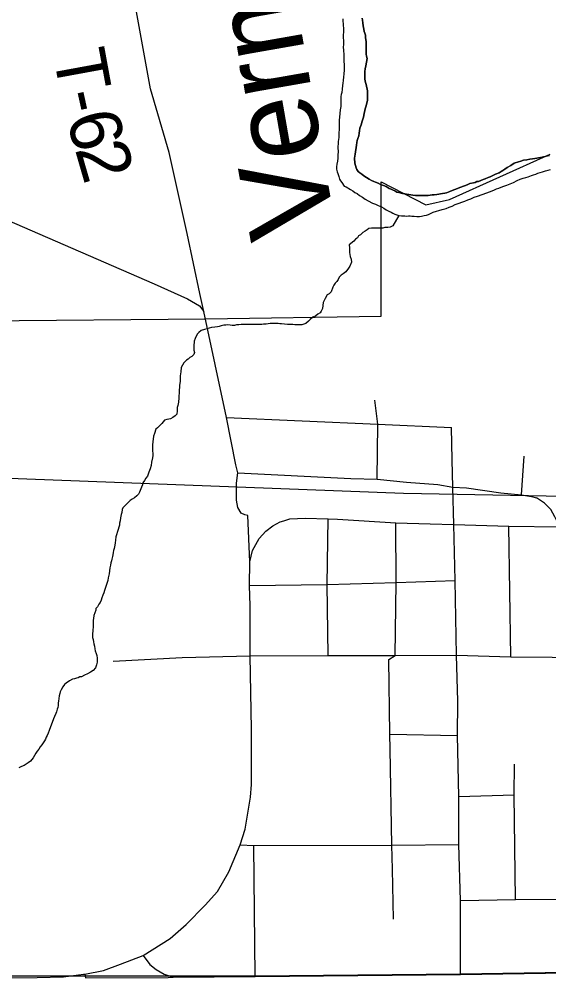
# Model space of a CAD drawing. Extents: x 0 to 34, y 0 to 22.
# Drawn here: x 4.314 to 4.895, y 17.722 to 18.774 of the extents above; entities that cross this region are included whole.
import ezdxf

# ---------------------------------------------------------------- set-up
doc = ezdxf.new("R2010")
doc.units = 0
for name, color, linetype in [('GM_X_City_Street', 7, 'Continuous'), ('GM_X_Corporation', 7, 'Continuous'), ('GM_X_Interchange_Ramps', 7, 'Continuous'), ('GM_X_Major_River', 7, 'Continuous'), ('GM_X_Major_River_Text', 7, 'Continuous'), ('GM_X_Minor_River', 7, 'Continuous'), ('GM_X_Rail_Line', 7, 'Continuous'), ('GM_X_State_Route', 7, 'Continuous'), ('GM_X_Township_Road', 7, 'Continuous'), ('GM_X_Township_Road_Text', 7, 'Continuous'), ('GM_X_US_Route', 7, 'Continuous')]:
    doc.layers.add(name, color=color, linetype=linetype)

msp = doc.modelspace()

# ---------------------------------------------------------------- linework, layer by layer
at = {"layer": 'GM_X_City_Street'}
for p, q in [((4.8651, 18.2518), (4.8682, 18.2942)), ((4.8537, 18.0739), (4.8512, 18.2173)), ((4.7206, 17.989), (4.7951, 17.9876)), ((4.7965, 17.9206), (4.8573, 17.9226)), ((4.5729, 17.7231), (4.5715, 17.867)), ((4.7246, 17.7862), (4.7235, 17.841))]:
    msp.add_line(p, q, dxfattribs=at)
for points in [[(4.567, 18.1782), (4.5648, 18.229), (4.5613, 18.2297), (4.5573, 18.2317), (4.5539, 18.2377), (4.5521, 18.2459), (4.5523, 18.2645), (4.5538, 18.2758), (4.5516, 18.2844), (4.5414, 18.3364), (4.5164, 18.4527)], [(4.7066, 18.2688), (4.7076, 18.3293), (4.7043, 18.3555)], [(4.5414, 18.3364), (4.7076, 18.3293), (4.7884, 18.3255)], [(4.7984, 17.7254), (4.7981, 17.8067), (4.7965, 17.8681), (4.7965, 17.9206), (4.7951, 17.9876), (4.7954, 18.0253), (4.7938, 18.0757), (4.7925, 18.1575), (4.7911, 18.219), (4.79, 18.2602), (4.7892, 18.29), (4.7884, 18.3255)], [(4.5538, 18.2758), (4.678, 18.2695), (4.7066, 18.2688), (4.739, 18.2655), (4.7733, 18.263), (4.79, 18.2602)], [(4.79, 18.2602), (4.805, 18.2594), (4.8425, 18.254), (4.8651, 18.2518), (4.8761, 18.2499), (4.8818, 18.2485)], [(4.9075, 18.2165), (4.902, 18.2277), (4.8974, 18.2354), (4.8905, 18.2425), (4.8818, 18.2485)], [(4.6529, 18.0755), (4.652, 18.1531), (4.6529, 18.2255)], [(4.7209, 17.9725), (4.7206, 17.989), (4.7194, 18.0709), (4.7266, 18.0753), (4.7277, 18.1556), (4.7274, 18.2209)], [(4.5664, 18.152), (4.652, 18.1531), (4.7277, 18.1556), (4.7925, 18.1575)], [(4.4167, 18.0692), (4.4925, 18.073), (4.5673, 18.075), (4.6529, 18.0755), (4.7266, 18.0753), (4.7938, 18.0757), (4.8537, 18.0739), (4.9444, 18.0733)], [(4.7235, 17.841), (4.7229, 17.8672), (4.7209, 17.9725)], [(4.8587, 17.8075), (4.8573, 17.9226), (4.8577, 17.9561)], [(4.5564, 17.8676), (4.5715, 17.867), (4.7229, 17.8672), (4.7965, 17.8681)], [(4.7981, 17.8067), (4.8587, 17.8075), (4.9715, 17.8081), (5.0032, 17.8089), (5.0412, 17.8083), (5.0567, 17.8112)]]:
    msp.add_lwpolyline(points, dxfattribs=at)
at = {"layer": 'GM_X_Corporation'}
for points in [[(4.2721, 18.4427), (4.5184, 18.4448), (4.7111, 18.4477), (4.7113, 18.595), (4.7602, 18.5697), (4.7862, 18.5757), (4.8968, 18.6254)], [(5.0777, 17.7302), (4.7982, 17.7259), (4.5726, 17.7236), (4.3607, 17.7236), (4.2797, 17.7236)]]:
    msp.add_lwpolyline(points, dxfattribs=at)
at = {"layer": 'GM_X_Interchange_Ramps'}
msp.add_lwpolyline([(4.3856, 17.7259), (4.3863, 17.7217), (4.4774, 17.7222), (4.4828, 17.7225)], dxfattribs=at)
at = {"layer": 'GM_X_Major_River'}
for points in [[(4.669, 18.7741), (4.669, 18.7715), (4.6694, 18.7684), (4.6694, 18.7662), (4.6698, 18.7639), (4.6698, 18.7593), (4.6694, 18.7563), (4.6694, 18.7536), (4.6698, 18.7498), (4.6698, 18.7456), (4.6694, 18.743), (4.6698, 18.7395), (4.6701, 18.7346), (4.6701, 18.7296), (4.6705, 18.7213), (4.6705, 18.7178), (4.6701, 18.7133), (4.6697, 18.7102), (4.6693, 18.7064), (4.669, 18.7034), (4.6686, 18.7007), (4.6682, 18.6969), (4.6678, 18.6931), (4.6674, 18.6908), (4.667, 18.6886), (4.667, 18.6855), (4.667, 18.6813), (4.6667, 18.6779), (4.6663, 18.6741), (4.6659, 18.6699), (4.6655, 18.6661), (4.6651, 18.6627), (4.6651, 18.6597), (4.6651, 18.6555), (4.6651, 18.6517), (4.6647, 18.6494), (4.6647, 18.6475), (4.6647, 18.6437), (4.664, 18.6395), (4.664, 18.6365), (4.6636, 18.6342), (4.6636, 18.6315), (4.6639, 18.6292), (4.6639, 18.6273), (4.6636, 18.6254), (4.6636, 18.6235), (4.6636, 18.6209), (4.6632, 18.6178), (4.6624, 18.6144), (4.662, 18.6117), (4.662, 18.6091), (4.6628, 18.606), (4.6635, 18.6041), (4.6647, 18.6011), (4.6654, 18.5981), (4.6666, 18.5961), (4.6681, 18.5942), (4.6707, 18.5904), (4.6726, 18.5897), (4.6776, 18.5866), (4.6799, 18.5851), (4.6821, 18.5832), (4.6848, 18.5821), (4.6874, 18.5802), (4.6905, 18.5783), (4.6935, 18.576), (4.6969, 18.5741)], [(4.669, 18.7741), (4.669, 18.7715), (4.6694, 18.7684), (4.6694, 18.7662), (4.6698, 18.7639), (4.6698, 18.7593), (4.6694, 18.7563), (4.6694, 18.7536), (4.6698, 18.7498), (4.6698, 18.7456), (4.6694, 18.743), (4.6698, 18.7395), (4.6701, 18.7346), (4.6701, 18.7296), (4.6705, 18.7213), (4.6705, 18.7178), (4.6701, 18.7133), (4.6697, 18.7102), (4.6693, 18.7064), (4.669, 18.7034), (4.6686, 18.7007), (4.6682, 18.6969), (4.6678, 18.6931), (4.6674, 18.6908), (4.667, 18.6886), (4.667, 18.6855), (4.667, 18.6813), (4.6667, 18.6779), (4.6663, 18.6741), (4.6659, 18.6699), (4.6655, 18.6661), (4.6651, 18.6627), (4.6651, 18.6597), (4.6651, 18.6555), (4.6651, 18.6517), (4.6647, 18.6494), (4.6647, 18.6475), (4.6647, 18.6437), (4.664, 18.6395), (4.664, 18.6365), (4.6636, 18.6342), (4.6636, 18.6315), (4.6639, 18.6292), (4.6639, 18.6273), (4.6636, 18.6254), (4.6636, 18.6235), (4.6636, 18.6209), (4.6632, 18.6178), (4.6624, 18.6144), (4.662, 18.6117), (4.662, 18.6091), (4.6628, 18.606), (4.6635, 18.6041), (4.6647, 18.6011), (4.6654, 18.5981), (4.6666, 18.5961), (4.6681, 18.5942), (4.6707, 18.5904), (4.6726, 18.5897), (4.6776, 18.5866), (4.6799, 18.5851), (4.6821, 18.5832), (4.6848, 18.5821), (4.6874, 18.5802), (4.6905, 18.5783), (4.6935, 18.576), (4.6969, 18.5741)], [(4.6981, 18.598), (4.692, 18.6018), (4.6898, 18.6034), (4.6879, 18.6049), (4.686, 18.6064), (4.6844, 18.6087), (4.6837, 18.6106), (4.6829, 18.6129), (4.6822, 18.6155), (4.6818, 18.6209), (4.6826, 18.6254), (4.6841, 18.6353), (4.6845, 18.6383), (4.6849, 18.6406), (4.6856, 18.6425), (4.6868, 18.6456), (4.6871, 18.6486), (4.6875, 18.6509), (4.6879, 18.6539), (4.6883, 18.6558), (4.6891, 18.6577), (4.6902, 18.6615), (4.6917, 18.6661), (4.6925, 18.6699), (4.6933, 18.6733), (4.6936, 18.6752), (4.6948, 18.6783), (4.6963, 18.6847), (4.6963, 18.695), (4.6948, 18.7019), (4.694, 18.7041), (4.6933, 18.7076), (4.6933, 18.7106), (4.6933, 18.714), (4.6933, 18.7163), (4.6937, 18.719), (4.6944, 18.7224), (4.6952, 18.7262), (4.6956, 18.7304), (4.6952, 18.733), (4.6948, 18.7353), (4.6948, 18.7376), (4.6948, 18.7403), (4.6948, 18.7433), (4.6945, 18.7467), (4.6945, 18.749), (4.6941, 18.7532), (4.6941, 18.7559), (4.6933, 18.7581), (4.6926, 18.76), (4.6922, 18.7627), (4.6915, 18.7661), (4.6911, 18.7696), (4.6907, 18.7726), (4.6903, 18.7745)], [(4.6903, 18.7745), (4.6907, 18.7726), (4.6911, 18.7696), (4.6915, 18.7661), (4.6922, 18.7627), (4.6926, 18.76), (4.6933, 18.7581), (4.6941, 18.7559), (4.6941, 18.7532), (4.6945, 18.749), (4.6945, 18.7467), (4.6948, 18.7433), (4.6948, 18.7403), (4.6948, 18.7376), (4.6948, 18.7353), (4.6952, 18.733), (4.6956, 18.7304), (4.6952, 18.7262), (4.6944, 18.7224), (4.6937, 18.719), (4.6933, 18.7163), (4.6933, 18.714), (4.6933, 18.7106), (4.6933, 18.7076), (4.694, 18.7041), (4.6948, 18.7019), (4.6963, 18.695), (4.6963, 18.6847), (4.6948, 18.6783), (4.6936, 18.6752), (4.6933, 18.6733), (4.6925, 18.6699), (4.6917, 18.6661), (4.6902, 18.6615), (4.6891, 18.6577), (4.6883, 18.6558), (4.6879, 18.6539), (4.6875, 18.6509), (4.6871, 18.6486), (4.6868, 18.6456), (4.6856, 18.6425), (4.6849, 18.6406), (4.6845, 18.6383), (4.6841, 18.6353), (4.6826, 18.6254), (4.6818, 18.6209), (4.6822, 18.6155), (4.6829, 18.6129), (4.6837, 18.6106), (4.6844, 18.6087), (4.686, 18.6064), (4.6879, 18.6049), (4.6898, 18.6034), (4.692, 18.6018), (4.6981, 18.598)], [(4.8961, 18.6241), (4.8938, 18.6237), (4.8912, 18.623), (4.8862, 18.6218), (4.8839, 18.6215), (4.882, 18.6211), (4.8798, 18.6207), (4.8775, 18.6203), (4.8744, 18.6199), (4.871, 18.6192), (4.8676, 18.6188), (4.8646, 18.6177), (4.8619, 18.6169), (4.8573, 18.6154), (4.8535, 18.6131), (4.8497, 18.6108), (4.8471, 18.6089), (4.8448, 18.6074), (4.8429, 18.6063), (4.8406, 18.6051), (4.8368, 18.6036), (4.8345, 18.6025), (4.8307, 18.6006), (4.8288, 18.5998), (4.8254, 18.5983), (4.8231, 18.5975), (4.8205, 18.5964), (4.8182, 18.5956), (4.8163, 18.5953), (4.8144, 18.5945), (4.8125, 18.5941), (4.8087, 18.5934), (4.8064, 18.5922), (4.8037, 18.5911), (4.8015, 18.5903), (4.7988, 18.5892), (4.7919, 18.5865), (4.7893, 18.5854), (4.7866, 18.5846), (4.7828, 18.5831), (4.7809, 18.5827), (4.7786, 18.5824), (4.7764, 18.582), (4.7745, 18.5816), (4.7722, 18.5812), (4.7695, 18.5809), (4.7672, 18.5809), (4.765, 18.5805), (4.7627, 18.5801), (4.76, 18.5801), (4.7577, 18.5801), (4.7539, 18.5801), (4.752, 18.5801), (4.749, 18.5801), (4.746, 18.5805), (4.7437, 18.5809), (4.7414, 18.5813), (4.7391, 18.5816), (4.7372, 18.582), (4.7346, 18.5824), (4.7304, 18.5835), (4.7285, 18.5839), (4.7262, 18.5851), (4.7243, 18.5858), (4.722, 18.587), (4.7201, 18.5877), (4.7167, 18.59), (4.7137, 18.5912), (4.7106, 18.5923), (4.708, 18.5935), (4.7049, 18.5946), (4.703, 18.5954), (4.7004, 18.5965), (4.6981, 18.598)], [(4.6981, 18.598), (4.7004, 18.5965), (4.703, 18.5954), (4.7049, 18.5946), (4.708, 18.5935), (4.7106, 18.5923), (4.7137, 18.5912), (4.7167, 18.59), (4.7201, 18.5877), (4.722, 18.587), (4.7243, 18.5858), (4.7262, 18.5851), (4.7285, 18.5839), (4.7304, 18.5835), (4.7346, 18.5824), (4.7372, 18.582), (4.7391, 18.5816), (4.7414, 18.5813), (4.7437, 18.5809), (4.746, 18.5805), (4.749, 18.5801), (4.752, 18.5801), (4.7539, 18.5801), (4.7577, 18.5801), (4.76, 18.5801), (4.7627, 18.5801), (4.765, 18.5805), (4.7672, 18.5809), (4.7695, 18.5809), (4.7722, 18.5812), (4.7745, 18.5816), (4.7764, 18.582), (4.7786, 18.5824), (4.7809, 18.5827), (4.7828, 18.5831), (4.7866, 18.5846), (4.7893, 18.5854), (4.7919, 18.5865), (4.7988, 18.5892), (4.8015, 18.5903), (4.8037, 18.5911), (4.8064, 18.5922), (4.8087, 18.5934), (4.8125, 18.5941), (4.8144, 18.5945), (4.8163, 18.5953), (4.8182, 18.5956), (4.8205, 18.5964), (4.8231, 18.5975), (4.8254, 18.5983), (4.8288, 18.5998), (4.8307, 18.6006), (4.8345, 18.6025), (4.8368, 18.6036), (4.8406, 18.6051), (4.8429, 18.6063), (4.8448, 18.6074), (4.8471, 18.6089), (4.8497, 18.6108), (4.8535, 18.6131), (4.8573, 18.6154), (4.8619, 18.6169), (4.8646, 18.6177), (4.8676, 18.6188), (4.871, 18.6192), (4.8744, 18.6199), (4.8775, 18.6203), (4.8798, 18.6207), (4.882, 18.6211), (4.8839, 18.6215), (4.8862, 18.6218), (4.8912, 18.623), (4.8938, 18.6237), (4.8961, 18.6241)], [(4.6969, 18.5741), (4.7015, 18.5718), (4.7049, 18.5706), (4.708, 18.5691), (4.7114, 18.5676), (4.714, 18.5661), (4.7167, 18.5645), (4.7197, 18.563), (4.722, 18.5619), (4.7239, 18.5607), (4.7262, 18.5596), (4.7285, 18.5588), (4.7307, 18.5581), (4.7334, 18.5577), (4.7353, 18.5577), (4.7372, 18.5577), (4.7391, 18.5573), (4.741, 18.5577), (4.7429, 18.5577), (4.7448, 18.5573), (4.7475, 18.5573), (4.7505, 18.5569), (4.7532, 18.5569), (4.7554, 18.5573), (4.7585, 18.558), (4.7608, 18.5584), (4.763, 18.5592), (4.7653, 18.5603), (4.7684, 18.5618), (4.7718, 18.563), (4.7744, 18.5637), (4.7782, 18.5649), (4.7824, 18.566), (4.7858, 18.5671), (4.7893, 18.5683), (4.7923, 18.5702), (4.7969, 18.5717), (4.7999, 18.5728), (4.803, 18.574), (4.8064, 18.5755), (4.8098, 18.5766), (4.8132, 18.5782), (4.817, 18.5793), (4.8273, 18.5831), (4.8303, 18.5842), (4.8349, 18.5861), (4.8379, 18.5873), (4.8402, 18.588), (4.8429, 18.5892), (4.8459, 18.5903), (4.8493, 18.5914), (4.8528, 18.593), (4.8566, 18.5945), (4.8604, 18.5964), (4.8638, 18.5979), (4.8672, 18.599), (4.8699, 18.5998), (4.8725, 18.6005), (4.8763, 18.6021), (4.8786, 18.6028), (4.8809, 18.6036), (4.8832, 18.6047), (4.8858, 18.6055), (4.8885, 18.6062), (4.8915, 18.607), (4.8946, 18.6078), (4.8972, 18.6085)], [(4.6969, 18.5741), (4.7015, 18.5718), (4.7049, 18.5706), (4.708, 18.5691), (4.7114, 18.5676), (4.714, 18.5661), (4.7167, 18.5645), (4.7197, 18.563), (4.722, 18.5619), (4.7239, 18.5607), (4.7262, 18.5596), (4.7285, 18.5588), (4.7307, 18.5581), (4.7334, 18.5577), (4.7353, 18.5577), (4.7372, 18.5577), (4.7391, 18.5573), (4.741, 18.5577), (4.7429, 18.5577), (4.7448, 18.5573), (4.7475, 18.5573), (4.7505, 18.5569), (4.7532, 18.5569), (4.7554, 18.5573), (4.7585, 18.558), (4.7608, 18.5584), (4.763, 18.5592), (4.7653, 18.5603), (4.7684, 18.5618), (4.7718, 18.563), (4.7744, 18.5637), (4.7782, 18.5649), (4.7824, 18.566), (4.7858, 18.5671), (4.7893, 18.5683), (4.7923, 18.5702), (4.7969, 18.5717), (4.7999, 18.5728), (4.803, 18.574), (4.8064, 18.5755), (4.8098, 18.5766), (4.8132, 18.5782), (4.817, 18.5793), (4.8273, 18.5831), (4.8303, 18.5842), (4.8349, 18.5861), (4.8379, 18.5873), (4.8402, 18.588), (4.8429, 18.5892), (4.8459, 18.5903), (4.8493, 18.5914), (4.8528, 18.593), (4.8566, 18.5945), (4.8604, 18.5964), (4.8638, 18.5979), (4.8672, 18.599), (4.8699, 18.5998), (4.8725, 18.6005), (4.8763, 18.6021), (4.8786, 18.6028), (4.8809, 18.6036), (4.8832, 18.6047), (4.8858, 18.6055), (4.8885, 18.6062), (4.8915, 18.607), (4.8946, 18.6078), (4.8972, 18.6085)]]:
    msp.add_lwpolyline(points, dxfattribs=at)
at = {"layer": 'GM_X_Minor_River'}
for points in [[(4.7307, 18.5581), (4.7239, 18.5467), (4.7209, 18.5455), (4.7186, 18.5451), (4.7151, 18.5448), (4.7129, 18.5444), (4.7106, 18.5444), (4.7072, 18.5444), (4.7045, 18.5444), (4.7026, 18.5444), (4.7007, 18.5444), (4.6977, 18.544), (4.6958, 18.5425), (4.6935, 18.541), (4.6912, 18.5395), (4.6885, 18.5368), (4.6863, 18.5357), (4.6851, 18.5338), (4.6828, 18.5322), (4.6813, 18.53), (4.676, 18.5258), (4.6764, 18.5227), (4.6764, 18.5174), (4.6767, 18.5155), (4.6771, 18.5132), (4.6783, 18.5102), (4.6786, 18.5068), (4.6767, 18.5026), (4.6752, 18.5003), (4.6725, 18.4965), (4.6695, 18.4942), (4.6672, 18.4927), (4.6649, 18.4904), (4.6638, 18.4881), (4.6623, 18.4859), (4.6607, 18.484), (4.6592, 18.4817), (4.6581, 18.4794), (4.6562, 18.4745), (4.6539, 18.4722), (4.652, 18.471), (4.6497, 18.4672), (4.6486, 18.465), (4.6474, 18.4627), (4.6467, 18.4562), (4.6451, 18.4532), (4.644, 18.4513), (4.6417, 18.4497), (4.6394, 18.4482), (4.636, 18.4467), (4.6333, 18.444), (4.6314, 18.4421), (4.6284, 18.4395), (4.6242, 18.438), (4.6223, 18.438), (4.62, 18.438), (4.6181, 18.438), (4.6162, 18.438), (4.6143, 18.4384), (4.6124, 18.4384), (4.6105, 18.4384), (4.6083, 18.4384), (4.6018, 18.4391), (4.5999, 18.4391), (4.598, 18.4395), (4.5953, 18.4395), (4.5934, 18.4395), (4.5915, 18.4395), (4.5893, 18.4395), (4.587, 18.4391), (4.5847, 18.4388), (4.582, 18.4388), (4.5801, 18.4384), (4.5779, 18.4384), (4.576, 18.4384), (4.5737, 18.4384), (4.571, 18.4384), (4.5684, 18.4384), (4.5665, 18.4384), (4.5638, 18.4384), (4.5611, 18.4384), (4.5592, 18.4384), (4.5573, 18.4384), (4.5547, 18.438), (4.5524, 18.438), (4.5501, 18.4376), (4.5475, 18.4376), (4.5452, 18.4377), (4.5429, 18.438), (4.5406, 18.4377), (4.5383, 18.4377), (4.5353, 18.4369)], [(4.5353, 18.4369), (4.5334, 18.4365), (4.5315, 18.4361), (4.5285, 18.4358), (4.525, 18.4354), (4.5224, 18.4346), (4.5171, 18.4331), (4.5136, 18.432), (4.511, 18.4297), (4.5091, 18.4278), (4.5068, 18.4232), (4.5057, 18.4202), (4.5053, 18.4149), (4.5056, 18.4103), (4.506, 18.408), (4.5053, 18.4057), (4.5034, 18.4035), (4.5011, 18.4023), (4.4992, 18.4004), (4.4973, 18.3993), (4.4946, 18.3966), (4.4916, 18.3913), (4.4912, 18.3867), (4.4904, 18.3822), (4.4904, 18.3791), (4.4904, 18.3761), (4.49, 18.3742), (4.4896, 18.3715), (4.4896, 18.3692), (4.4893, 18.3673), (4.4893, 18.3632), (4.4889, 18.3601), (4.4889, 18.3582), (4.4885, 18.3533), (4.4877, 18.3498), (4.4873, 18.3476), (4.4873, 18.3438), (4.4869, 18.3403), (4.485, 18.3384), (4.4824, 18.3365), (4.4797, 18.335), (4.4778, 18.3346), (4.4759, 18.3343), (4.4733, 18.3335), (4.4702, 18.3301), (4.4676, 18.3274), (4.4657, 18.3251), (4.4638, 18.3236), (4.4622, 18.3191), (4.4611, 18.316), (4.4603, 18.3099), (4.4599, 18.3065), (4.4599, 18.3042), (4.4599, 18.3023), (4.4603, 18.2947), (4.4599, 18.2924), (4.4588, 18.2875), (4.4584, 18.2837), (4.4576, 18.2803), (4.4569, 18.2784), (4.4561, 18.2765), (4.4546, 18.2723), (4.4527, 18.27), (4.4512, 18.2673), (4.4496, 18.2647), (4.4492, 18.2628), (4.4481, 18.2601), (4.4473, 18.2582), (4.4458, 18.2544), (4.4447, 18.2525), (4.4428, 18.2506), (4.4401, 18.2483), (4.4378, 18.2468), (4.4356, 18.2453), (4.4333, 18.2434), (4.4314, 18.2415), (4.4295, 18.2396), (4.4276, 18.2373), (4.4268, 18.2354), (4.4264, 18.2324), (4.4257, 18.2301), (4.4249, 18.2263), (4.4245, 18.2232), (4.4237, 18.2206), (4.4237, 18.2183), (4.423, 18.216), (4.4222, 18.2137), (4.4199, 18.2054), (4.4195, 18.202), (4.4192, 18.1989), (4.4188, 18.1966), (4.418, 18.1928), (4.4173, 18.1905), (4.4169, 18.1883), (4.4165, 18.186), (4.4161, 18.1841), (4.4153, 18.181), (4.415, 18.1791), (4.4142, 18.1769), (4.4138, 18.1746), (4.4131, 18.1715)], [(4.4131, 18.1715), (4.4123, 18.1651), (4.4115, 18.1605), (4.4108, 18.1575), (4.41, 18.1544), (4.4092, 18.1521), (4.4085, 18.1499), (4.4073, 18.1468), (4.4066, 18.1442), (4.4054, 18.1415), (4.4043, 18.1385), (4.4035, 18.1362), (4.4024, 18.1335), (4.4012, 18.1316), (4.3997, 18.1289), (4.3978, 18.127), (4.3978, 18.1251), (4.3955, 18.1191), (4.3951, 18.116), (4.3948, 18.1141), (4.3947, 18.1118), (4.3947, 18.1099), (4.3947, 18.1061), (4.3944, 18.1039), (4.3944, 18.1016), (4.394, 18.0997), (4.3943, 18.0951), (4.3947, 18.0928), (4.3951, 18.0905), (4.3955, 18.0883), (4.3962, 18.0856), (4.3966, 18.0826), (4.397, 18.0806), (4.3981, 18.0776), (4.3989, 18.0753), (4.3993, 18.0723), (4.3993, 18.0704), (4.3993, 18.0681), (4.3985, 18.0651), (4.3974, 18.062), (4.3947, 18.059), (4.392, 18.0571), (4.3886, 18.0552), (4.3852, 18.0537), (4.3821, 18.0521), (4.3802, 18.0518), (4.3783, 18.051), (4.3764, 18.0506), (4.3742, 18.0499), (4.3723, 18.0495), (4.3688, 18.0476), (4.3654, 18.0449), (4.3635, 18.0434), (4.3616, 18.0411), (4.3597, 18.0377), (4.3586, 18.0354), (4.3582, 18.0335), (4.3574, 18.0312), (4.357, 18.0282), (4.3567, 18.0252), (4.3563, 18.0233), (4.3563, 18.0206), (4.3559, 18.0183), (4.3555, 18.0164), (4.3547, 18.0137), (4.354, 18.0118), (4.3525, 18.0084), (4.3513, 18.0058), (4.3467, 17.9932), (4.3456, 17.9902), (4.3445, 17.9875), (4.3433, 17.9856), (4.3426, 17.9837), (4.3414, 17.9818), (4.3399, 17.9795), (4.3384, 17.9772), (4.3365, 17.975), (4.3353, 17.9727), (4.3334, 17.9704), (4.3319, 17.9681), (4.3304, 17.9655), (4.3289, 17.9632), (4.3277, 17.9613), (4.3262, 17.9594), (4.3235, 17.9575), (4.319, 17.9548), (4.3163, 17.9537), (4.3133, 17.9522)]]:
    msp.add_lwpolyline(points, dxfattribs=at)
at = {"layer": 'GM_X_Rail_Line'}
msp.add_lwpolyline([(2.1, 18.3652), (2.4476, 18.3515), (3.7542, 18.2908), (4.7355, 18.2536), (4.912, 18.2502), (5.0326, 18.2535), (5.2097, 18.2563), (5.4881, 18.3005), (6.2957, 18.4383), (6.9068, 18.5576), (7.5368, 18.6745), (7.9374, 18.7476)], dxfattribs=at)
at = {"layer": 'GM_X_State_Route'}
for points in [[(4.4499, 17.7463), (4.4571, 17.7363), (4.4641, 17.7308), (4.4727, 17.7258), (4.4828, 17.7225)], [(4.4828, 17.7225), (4.5729, 17.7231), (4.7984, 17.7254), (5.078, 17.7297)]]:
    msp.add_lwpolyline(points, dxfattribs=at)
at = {"layer": 'GM_X_Township_Road'}
for points in [[(4.5164, 18.4527), (4.5119, 18.4725), (4.498, 18.5384), (4.4783, 18.6273), (4.4577, 18.6971), (4.4306, 18.8465), (4.4032, 19.0032), (4.394, 19.0488), (4.3932, 19.0568), (4.3941, 19.0716), (4.4022, 19.116), (4.427, 19.2307), (4.4554, 19.4164), (4.4883, 19.6622), (4.4951, 19.7226)], [(2.7026, 18.7182), (2.939, 18.7191), (3.2644, 18.7179), (3.5814, 18.719), (3.738, 18.7184), (3.796, 18.7166), (3.8897, 18.7163), (3.9185, 18.7162), (3.9265, 18.7154), (3.9481, 18.7058), (4.4619, 18.4832), (4.4984, 18.4668), (4.5115, 18.459), (4.5164, 18.4527)]]:
    msp.add_lwpolyline(points, dxfattribs=at)
at = {"layer": 'GM_X_US_Route'}
for points in [[(4.5688, 17.974), (4.5688, 17.9945), (4.5673, 18.075), (4.5673, 18.1298), (4.5664, 18.152), (4.567, 18.1782), (4.57, 18.1906), (4.5773, 18.2039), (4.5844, 18.2118), (4.5921, 18.2178), (4.6003, 18.222), (4.6041, 18.2232)], [(4.6041, 18.2232), (4.611, 18.2253), (4.6277, 18.226), (4.6529, 18.2255), (4.6631, 18.2249)], [(4.6631, 18.2249), (4.7274, 18.2209), (4.7648, 18.2198)], [(4.7648, 18.2198), (4.7911, 18.219), (4.8512, 18.2173), (4.9075, 18.2165)], [(4.5564, 17.8676), (4.5617, 17.8847), (4.5656, 17.9069), (4.5676, 17.9198), (4.5688, 17.934), (4.5688, 17.974)], [(4.3856, 17.7259), (4.4063, 17.7299), (4.425, 17.7367), (4.4499, 17.7463), (4.4794, 17.765), (4.4969, 17.7803), (4.5179, 17.8013), (4.5315, 17.8166), (4.544, 17.8381), (4.5564, 17.8676)], [(4.2949, 17.7218), (4.3333, 17.7221), (4.3623, 17.7229), (4.3841, 17.7256), (4.3856, 17.7259)]]:
    msp.add_lwpolyline(points, dxfattribs=at)

# ---------------------------------------------------------------- texts
at = {"layer": 'GM_X_Major_River_Text'}
msp.add_text('Vermilion', height=0.09475, rotation=99.9481, dxfattribs=at).set_placement((4.6617, 18.5433))
at = {"layer": 'GM_X_Township_Road_Text'}
for s, rotation, p in [('T', 280.4198, (4.3508, 18.7354)), ('-', 282.4744, (4.3589, 18.6915)), ('6', 285.9626, (4.3649, 18.665)), ('2', 286.2183, (4.3746, 18.6311))]:
    msp.add_text(s, height=0.0568, rotation=rotation, dxfattribs=at).set_placement(p)

doc.saveas('drawing.dxf')
